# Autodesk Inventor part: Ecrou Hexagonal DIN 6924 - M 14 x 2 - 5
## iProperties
Created: 2002-04
Part Number: Ecrou Hexagonal DIN 6924 - M 14 x 2 - 5
Material: Par défaut
Catalog Web Link: www.traceparts.com
Description: Ecrou Hexagonal DIN 6924 - M 14 x 2 - 5
Document SubType Name: Modélisation
Designer: Maison
Control State: 0
Master: False
Checked Out: False
Shininess: 20.0
Length Units: 11269
Angle Units: 11279
Time Units: 11290
Mass Units: 11283
Length Display Precision: 3
Angle Display Precision: 2
Density: 0.0
Volumn: 0.0
Area: 0.0
PropertySet Name: Model Information
Author: Maison
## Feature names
1. Base1
